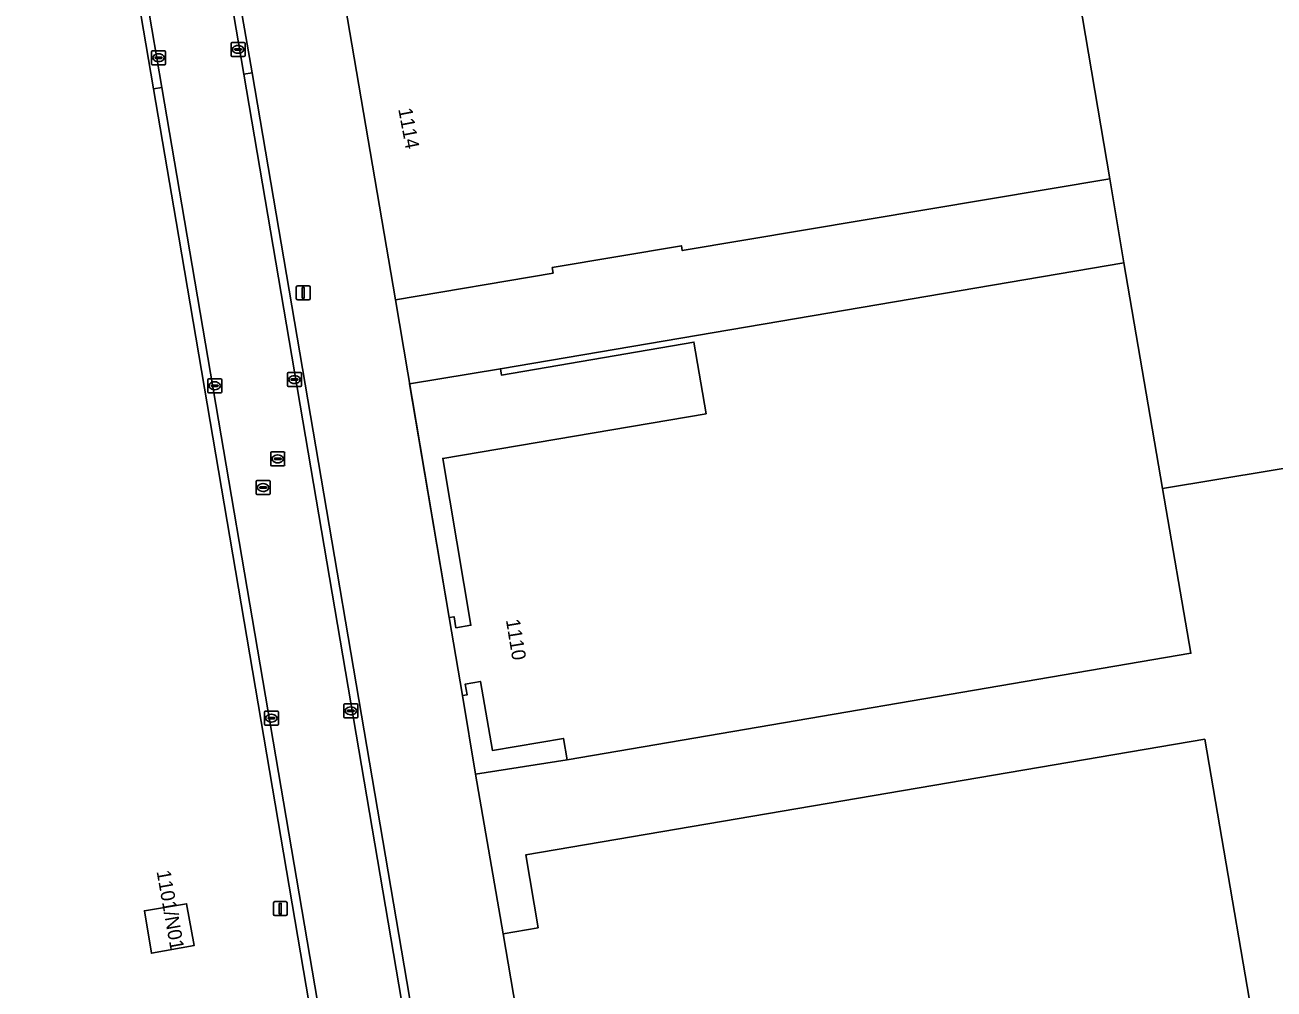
# Model space of a CAD drawing. Extents: x 154324 to 155744, y 382937 to 384188.
# Drawn here: x 154922.2 to 155011.6, y 383294.5 to 383363.4 of the extents above; entities that cross this region are included whole.
import ezdxf

# ---------------------------------------------------------------- set-up
doc = ezdxf.new("R2010")
doc.units = 0
for name, color, linetype in [('IMGEO_Erf', 7, 'Continuous'), ('IMGEO_Grasland_agrarisch', 7, 'Continuous'), ('IMGEO_Kolk', 7, 'Continuous'), ('IMGEO_Lichtmast', 7, 'Continuous'), ('IMGEO_Pand', 7, 'Continuous'), ('IMGEO_Pand_nummerreeks', 7, 'Continuous'), ('IMGEO_Pand_overbouw', 7, 'Continuous'), ('IMGEO_Parkeervlak_open', 7, 'Continuous'), ('IMGEO_Rijbaan_lokaal_gesloten', 7, 'Continuous'), ('IMGEO_Rijbaan_lokaal_open', 7, 'Continuous'), ('IMGEO_Rioolput', 7, 'Continuous')]:
    doc.layers.add(name, color=color, linetype=linetype)

msp = doc.modelspace()

# ---------------------------------------------------------------- linework, layer by layer
at = {"layer": 'IMGEO_Erf'}
for points in [[(154957.636, 383205.007), (154955.126, 383219.621), (154933.063, 383349.385), (154931.446, 383358.867), (154880.326, 383658.587)], [(155062.526, 383340.029), (155003.646, 383330.283), (155005.673, 383318.494), (154961.037, 383310.872), (154960.776, 383312.399), (154955.689, 383311.55), (154954.834, 383316.483), (154953.74, 383316.294), (154953.892, 383315.524), (154953.555, 383315.462), (154954.479, 383309.839), (154956.449, 383298.428), (154958.963, 383298.857), (154958.072, 383304.074), (155006.663, 383312.344), (155011.213, 383285.747), (154970.24, 383278.793), (154971.18, 383273.272), (154961.04, 383271.548), (154962.295, 383264.145), (155007.491, 383271.866), (155014.059, 383233.409)]]:
    msp.add_lwpolyline(points, dxfattribs=at)
for points in [[(154970.103, 383340.756), (154956.338, 383338.399), (154956.261, 383338.852), (155000.868, 383346.436), (154999.878, 383352.447), (154969.278, 383347.303), (154969.219, 383347.653), (154959.969, 383346.088), (154960.036, 383345.69), (154948.75, 383343.779), (154952.604, 383321.047), (154952.949, 383321.105), (154953.081, 383320.316), (154954.156, 383320.496), (154952.132, 383332.433), (154970.973, 383335.629)], [(154930.785, 383300.07), (154933.808, 383300.574), (154934.341, 383297.582), (154931.29, 383297.039)]]:
    msp.add_lwpolyline(points, close=True, dxfattribs=at)
at = {"layer": 'IMGEO_Grasland_agrarisch'}
msp.add_lwpolyline([(154995.109, 383380.559), (154999.878, 383352.447), (155000.868, 383346.436), (155003.646, 383330.283), (155062.526, 383340.029), (155067.422, 383340.839), (155069.458, 383341.15), (155069.432, 383341.538), (155066.213, 383389.857)], dxfattribs=at)
at = {"layer": 'IMGEO_Kolk'}
for p, q in [((154931.301, 383360.675), (154931.301, 383361.527)), ((154931.376, 383361.601), (154932.228, 383361.601)), ((154931.789, 383361.381), (154931.814, 383361.381)), ((154932.302, 383361.527), (154932.302, 383360.675)), ((154936.986, 383361.271), (154936.986, 383362.123)), ((154937.061, 383362.197), (154937.913, 383362.197)), ((154937.245, 383361.691), (154937.245, 383361.703)), ((154937.683, 383361.654), (154937.285, 383361.654)), ((154937.288, 383361.74), (154937.686, 383361.74)), ((154937.497, 383361.417), (154937.472, 383361.417)), ((154937.474, 383361.977), (154937.499, 383361.977)), ((154937.729, 383361.703), (154937.729, 383361.691)), ((154937.987, 383362.123), (154937.987, 383361.271)), ((154932.228, 383360.601), (154931.376, 383360.601)), ((154931.56, 383361.095), (154931.56, 383361.107)), ((154931.998, 383361.058), (154931.6, 383361.058)), ((154931.603, 383361.144), (154932.001, 383361.144)), ((154931.812, 383360.821), (154931.787, 383360.821)), ((154932.044, 383361.107), (154932.044, 383361.095)), ((154937.913, 383361.197), (154937.061, 383361.197)), ((154935.395, 383338.133), (154936.247, 383338.133)), ((154941.026, 383337.649), (154941.026, 383338.501)), ((154941.101, 383338.575), (154941.953, 383338.575)), ((154941.514, 383338.355), (154941.539, 383338.355)), ((154942.027, 383338.501), (154942.027, 383337.649)), ((154935.32, 383337.207), (154935.32, 383338.059)), ((154935.579, 383337.627), (154935.579, 383337.639)), ((154936.017, 383337.59), (154935.619, 383337.59)), ((154935.622, 383337.676), (154936.02, 383337.676)), ((154935.831, 383337.353), (154935.806, 383337.353)), ((154935.808, 383337.913), (154935.833, 383337.913)), ((154936.063, 383337.639), (154936.063, 383337.627)), ((154936.321, 383338.059), (154936.321, 383337.207)), ((154941.953, 383337.575), (154941.101, 383337.575)), ((154941.285, 383338.069), (154941.285, 383338.081)), ((154941.723, 383338.032), (154941.325, 383338.032)), ((154941.328, 383338.118), (154941.726, 383338.118)), ((154941.537, 383337.795), (154941.512, 383337.795)), ((154941.769, 383338.081), (154941.769, 383338.069)), ((154936.247, 383337.133), (154935.395, 383337.133)), ((154939.374, 383313.426), (154939.374, 383314.278)), ((154939.449, 383314.352), (154940.301, 383314.352)), ((154939.862, 383314.132), (154939.887, 383314.132)), ((154940.375, 383314.278), (154940.375, 383313.426)), ((154945.059, 383313.946), (154945.059, 383314.798)), ((154945.134, 383314.872), (154945.986, 383314.872)), ((154945.318, 383314.366), (154945.318, 383314.378)), ((154945.756, 383314.329), (154945.358, 383314.329)), ((154945.361, 383314.415), (154945.759, 383314.415)), ((154945.57, 383314.092), (154945.545, 383314.092)), ((154945.547, 383314.652), (154945.572, 383314.652)), ((154945.802, 383314.378), (154945.802, 383314.366)), ((154946.06, 383314.798), (154946.06, 383313.946)), ((154940.301, 383313.352), (154939.449, 383313.352)), ((154939.633, 383313.846), (154939.633, 383313.858)), ((154940.071, 383313.809), (154939.673, 383313.809)), ((154939.676, 383313.895), (154940.074, 383313.895)), ((154939.885, 383313.572), (154939.86, 383313.572)), ((154940.117, 383313.858), (154940.117, 383313.846)), ((154945.986, 383313.872), (154945.134, 383313.872))]:
    msp.add_line(p, q, dxfattribs=at)
for points in [[(154931.301, 383360.675), (154931.301, 383361.527)], [(154931.376, 383361.601), (154932.228, 383361.601)], [(154932.302, 383361.527), (154932.302, 383360.675)], [(154936.986, 383361.271), (154936.986, 383362.123)], [(154937.061, 383362.197), (154937.913, 383362.197)], [(154937.987, 383362.123), (154937.987, 383361.271)], [(154932.228, 383360.601), (154931.376, 383360.601)], [(154937.913, 383361.197), (154937.061, 383361.197)], [(154935.395, 383338.133), (154936.247, 383338.133)], [(154941.026, 383337.649), (154941.026, 383338.501)], [(154941.101, 383338.575), (154941.953, 383338.575)], [(154942.027, 383338.501), (154942.027, 383337.649)], [(154935.32, 383337.207), (154935.32, 383338.059)], [(154936.321, 383338.059), (154936.321, 383337.207)], [(154941.953, 383337.575), (154941.101, 383337.575)], [(154936.247, 383337.133), (154935.395, 383337.133)], [(154939.374, 383313.426), (154939.374, 383314.278)], [(154939.449, 383314.352), (154940.301, 383314.352)], [(154940.375, 383314.278), (154940.375, 383313.426)], [(154945.059, 383313.946), (154945.059, 383314.798)], [(154945.134, 383314.872), (154945.986, 383314.872)], [(154946.06, 383314.798), (154946.06, 383313.946)], [(154940.301, 383313.352), (154939.449, 383313.352)], [(154945.986, 383313.872), (154945.134, 383313.872)]]:
    msp.add_lwpolyline(points, dxfattribs=at)
for centre, radius, start, end in [((154931.378, 383361.525), 0.0765, 91.55205, 178.44795), ((154931.378, 383361.525), 0.0765, 91.55205, 178.44795), ((154932.226, 383361.525), 0.0765, 1.55205, 88.44795), ((154932.226, 383361.525), 0.0765, 1.55205, 88.44795), ((154937.063, 383362.121), 0.0765, 91.55205, 178.44795), ((154937.063, 383362.121), 0.0765, 91.55205, 178.44795), ((154937.285, 383361.7), 0.0403, 85.87752, 175.75265), ((154937.282, 383361.69), 0.0366, 178.93798, 274.71019), ((154937.686, 383361.697), 0.043, 264.86636, 352.45326), ((154937.69, 383361.702), 0.0386, 1.73085, 96.63898), ((154937.911, 383362.121), 0.0765, 1.55205, 88.44795), ((154937.911, 383362.121), 0.0765, 1.55205, 88.44795), ((154931.378, 383360.677), 0.0765, 181.55205, 268.44795), ((154931.378, 383360.677), 0.0765, 181.55205, 268.44795), ((154931.6, 383361.104), 0.0403, 85.87752, 175.75265), ((154931.597, 383361.094), 0.0366, 178.93798, 274.71019), ((154932.001, 383361.101), 0.043, 264.86636, 352.45326), ((154932.005, 383361.106), 0.0386, 1.73085, 96.63898), ((154932.226, 383360.677), 0.0765, 271.55205, 358.44795), ((154932.226, 383360.677), 0.0765, 271.55205, 358.44795), ((154937.063, 383361.273), 0.0765, 181.55205, 268.44795), ((154937.063, 383361.273), 0.0765, 181.55205, 268.44795), ((154937.911, 383361.273), 0.0765, 271.55205, 358.44795), ((154937.911, 383361.273), 0.0765, 271.55205, 358.44795), ((154935.397, 383338.057), 0.0765, 91.55205, 178.44795), ((154935.397, 383338.057), 0.0765, 91.55205, 178.44795), ((154936.245, 383338.057), 0.0765, 1.55205, 88.44795), ((154936.245, 383338.057), 0.0765, 1.55205, 88.44795), ((154941.103, 383338.499), 0.0765, 91.55205, 178.44795), ((154941.103, 383338.499), 0.0765, 91.55205, 178.44795), ((154941.951, 383338.499), 0.0765, 1.55205, 88.44795), ((154941.951, 383338.499), 0.0765, 1.55205, 88.44795), ((154935.619, 383337.636), 0.0403, 85.87752, 175.75265), ((154935.616, 383337.626), 0.0366, 178.93798, 274.71019), ((154936.02, 383337.633), 0.043, 264.86636, 352.45326), ((154936.024, 383337.638), 0.0386, 1.73085, 96.63898), ((154941.103, 383337.651), 0.0765, 181.55205, 268.44795), ((154941.103, 383337.651), 0.0765, 181.55205, 268.44795), ((154941.325, 383338.078), 0.0403, 85.87752, 175.75265), ((154941.322, 383338.068), 0.0366, 178.93798, 274.71019), ((154941.726, 383338.075), 0.043, 264.86636, 352.45326), ((154941.73, 383338.08), 0.0386, 1.73085, 96.63898), ((154941.951, 383337.651), 0.0765, 271.55205, 358.44795), ((154941.951, 383337.651), 0.0765, 271.55205, 358.44795), ((154935.397, 383337.209), 0.0765, 181.55205, 268.44795), ((154935.397, 383337.209), 0.0765, 181.55205, 268.44795), ((154936.245, 383337.209), 0.0765, 271.55205, 358.44795), ((154936.245, 383337.209), 0.0765, 271.55205, 358.44795), ((154939.451, 383314.276), 0.0765, 91.55205, 178.44795), ((154939.451, 383314.276), 0.0765, 91.55205, 178.44795), ((154940.299, 383314.276), 0.0765, 1.55205, 88.44795), ((154940.299, 383314.276), 0.0765, 1.55205, 88.44795), ((154945.136, 383314.796), 0.0765, 91.55205, 178.44795), ((154945.136, 383314.796), 0.0765, 91.55205, 178.44795), ((154945.358, 383314.375), 0.0403, 85.87752, 175.75265), ((154945.355, 383314.365), 0.0366, 178.93798, 274.71019), ((154945.759, 383314.372), 0.043, 264.86636, 352.45326), ((154945.763, 383314.377), 0.0386, 1.73085, 96.63898), ((154945.984, 383314.796), 0.0765, 1.55205, 88.44795), ((154945.984, 383314.796), 0.0765, 1.55205, 88.44795), ((154939.451, 383313.428), 0.0765, 181.55205, 268.44795), ((154939.451, 383313.428), 0.0765, 181.55205, 268.44795), ((154939.673, 383313.855), 0.0403, 85.87752, 175.75265), ((154939.67, 383313.845), 0.0366, 178.93798, 274.71019), ((154940.074, 383313.852), 0.043, 264.86636, 352.45326), ((154940.078, 383313.857), 0.0386, 1.73085, 96.63898), ((154940.299, 383313.428), 0.0765, 271.55205, 358.44795), ((154940.299, 383313.428), 0.0765, 271.55205, 358.44795), ((154945.136, 383313.948), 0.0765, 181.55205, 268.44795), ((154945.136, 383313.948), 0.0765, 181.55205, 268.44795), ((154945.984, 383313.948), 0.0765, 271.55205, 358.44795), ((154945.984, 383313.948), 0.0765, 271.55205, 358.44795)]:
    msp.add_arc(centre, radius, start, end, dxfattribs=at)
for centre, major_axis, ratio, start_param, end_param in [((154931.788, 383361.101), (-0.387, 0.002), 0.722429, 4.712389, 7.853982), ((154931.813, 383361.101), (-0.39, 0.002), 0.717154, 1.570796, 4.712389), ((154937.473, 383361.697), (-0.387, 0.002), 0.722429, 4.712389, 7.853982), ((154937.498, 383361.697), (-0.39, 0.002), 0.717154, 1.570796, 4.712389), ((154941.513, 383338.075), (-0.387, 0.002), 0.722429, 4.712389, 7.853982), ((154941.538, 383338.075), (-0.39, 0.002), 0.717154, 1.570796, 4.712389), ((154935.807, 383337.633), (-0.387, 0.002), 0.722429, 4.712389, 7.853982), ((154935.832, 383337.633), (-0.39, 0.002), 0.717154, 1.570796, 4.712389), ((154939.861, 383313.852), (-0.387, 0.002), 0.722429, 4.712389, 7.853982), ((154939.886, 383313.852), (-0.39, 0.002), 0.717154, 1.570796, 4.712389), ((154945.546, 383314.372), (-0.387, 0.002), 0.722429, 4.712389, 7.853982), ((154945.571, 383314.372), (-0.39, 0.002), 0.717154, 1.570796, 4.712389)]:
    msp.add_ellipse(centre, major_axis=major_axis, ratio=ratio, start_param=start_param, end_param=end_param, dxfattribs=at)
at = {"layer": 'IMGEO_Lichtmast'}
for p, q in [((154941.658, 383343.88), (154941.658, 383344.68)), ((154941.658, 383344.68), (154941.658, 383343.88)), ((154941.758, 383344.78), (154942.548, 383344.78)), ((154942.548, 383344.78), (154941.758, 383344.78)), ((154942.648, 383344.68), (154942.648, 383343.88)), ((154942.648, 383343.88), (154942.648, 383344.68)), ((154942.548, 383343.78), (154941.758, 383343.78)), ((154941.758, 383343.78), (154942.548, 383343.78)), ((154940.014, 383299.826), (154940.014, 383300.626)), ((154940.014, 383300.626), (154940.014, 383299.826)), ((154940.114, 383300.726), (154940.904, 383300.726)), ((154940.904, 383300.726), (154940.114, 383300.726)), ((154941.004, 383300.626), (154941.004, 383299.826)), ((154941.004, 383299.826), (154941.004, 383300.626)), ((154940.904, 383299.726), (154940.114, 383299.726)), ((154940.114, 383299.726), (154940.904, 383299.726))]:
    msp.add_line(p, q, dxfattribs=at)
for points in [[(154942.078, 383344.655), (154942.228, 383344.655), (154942.228, 383343.905), (154942.078, 383343.905), (154942.078, 383344.655)], [(154940.434, 383300.601), (154940.584, 383300.601), (154940.584, 383299.851), (154940.434, 383299.851), (154940.434, 383300.601)]]:
    msp.add_lwpolyline(points, dxfattribs=at)
for centre, start, end in [((154941.758, 383344.68), 90, 180), ((154941.758, 383344.68), 90, 180), ((154942.548, 383344.68), 0, 90), ((154942.548, 383344.68), 360, 90), ((154941.758, 383343.88), 180, 270), ((154941.758, 383343.88), 180, 270), ((154942.548, 383343.88), 270, 0), ((154942.548, 383343.88), 270, 0), ((154940.114, 383300.626), 90, 180), ((154940.114, 383300.626), 90, 180), ((154940.904, 383300.626), 0, 90), ((154940.904, 383300.626), 360, 90), ((154940.114, 383299.826), 180, 270), ((154940.114, 383299.826), 180, 270), ((154940.904, 383299.826), 270, 0), ((154940.904, 383299.826), 270, 0)]:
    msp.add_arc(centre, 0.1, start, end, dxfattribs=at)
at = {"layer": 'IMGEO_Pand'}
for points in [[(154995.109, 383380.559), (154964.539, 383375.316), (154965.468, 383369.782), (154944.925, 383366.268), (154944.993, 383365.869), (154948.75, 383343.779), (154960.036, 383345.69), (154959.969, 383346.088), (154969.219, 383347.653), (154969.278, 383347.303), (154999.878, 383352.447)], [(155000.868, 383346.436), (154956.261, 383338.852), (154956.338, 383338.399), (154970.103, 383340.756), (154970.973, 383335.629), (154952.132, 383332.433), (154954.156, 383320.496), (154953.081, 383320.316), (154952.949, 383321.105), (154952.604, 383321.047), (154953.555, 383315.462), (154953.892, 383315.524), (154953.74, 383316.294), (154954.834, 383316.483), (154955.689, 383311.55), (154960.776, 383312.399), (154961.037, 383310.872), (155005.673, 383318.494), (155003.646, 383330.283)], [(154958.072, 383304.074), (154958.963, 383298.857), (154956.449, 383298.428), (154961.04, 383271.548), (154971.18, 383273.272), (154970.24, 383278.793), (155011.213, 383285.747), (155006.663, 383312.344)], [(154931.29, 383297.039), (154934.341, 383297.582), (154933.808, 383300.574), (154930.785, 383300.07)]]:
    msp.add_lwpolyline(points, close=True, dxfattribs=at)
at = {"layer": 'IMGEO_Pand_overbouw'}
for points in [[(154956.261, 383338.852), (154949.764, 383337.775), (154952.604, 383321.047), (154952.949, 383321.105), (154953.081, 383320.316), (154954.156, 383320.496), (154952.132, 383332.433), (154970.973, 383335.629), (154970.103, 383340.756), (154956.338, 383338.399)], [(154961.037, 383310.872), (154960.776, 383312.399), (154955.689, 383311.55), (154954.834, 383316.483), (154953.74, 383316.294), (154953.892, 383315.524), (154953.555, 383315.462), (154954.479, 383309.839)]]:
    msp.add_lwpolyline(points, close=True, dxfattribs=at)
at = {"layer": 'IMGEO_Parkeervlak_open'}
msp.add_lwpolyline([(154970.556, 383221.2), (154970.312, 383222.697), (154969.397, 383222.533), (154962.295, 383264.145), (154961.04, 383271.548), (154956.449, 383298.428), (154954.479, 383309.839), (154953.555, 383315.462), (154952.604, 383321.047), (154948.75, 383343.779), (154944.993, 383365.869), (154944.925, 383366.268), (154965.468, 383369.782), (154964.539, 383375.316), (154941.3, 383371.33), (154939.601, 383371.039), (154936.699, 383370.542), (154936.71, 383370.477), (154937.698, 383364.674), (154938.491, 383360.02), (154942.478, 383336.616), (154962.428, 383219.494)], dxfattribs=at)
at = {"layer": 'IMGEO_Rijbaan_lokaal_gesloten'}
for points in [[(154854.425, 383814.31), (154854.653, 383812.991), (154854.813, 383812.024), (154858.483, 383790.497), (154869.559, 383725.258), (154869.596, 383725.133), (154932.04, 383358.964), (154933.662, 383349.45), (154956.051, 383217.962), (154957.681, 383208.024), (154958.22, 383204.737)], [(154961.836, 383219.4), (154937.891, 383359.922), (154875.734, 383724.688)]]:
    msp.add_lwpolyline(points, dxfattribs=at)
at = {"layer": 'IMGEO_Rijbaan_lokaal_open'}
for points in [[(154859.21, 383821.776), (154860.592, 383813.666), (154872.994, 383740.868), (154875.261, 383727.607), (154875.734, 383724.688), (154937.891, 383359.922), (154938.491, 383360.02), (154937.698, 383364.674), (154936.71, 383370.477), (154936.699, 383370.542), (154936.688, 383370.604), (154886.005, 383668.098)], [(154853.936, 383813.593), (154856.176, 383800.396), (154857.871, 383790.412), (154868.954, 383725.158), (154878.393, 383669.904), (154880.297, 383658.755), (154880.326, 383658.587), (154931.446, 383358.867), (154932.04, 383358.964), (154869.596, 383725.133), (154869.559, 383725.258), (154858.483, 383790.497), (154854.813, 383812.024), (154854.653, 383812.991), (154854.425, 383814.31)], [(154938.491, 383360.02), (154937.891, 383359.922), (154961.836, 383219.4)], [(154962.428, 383219.494), (154942.478, 383336.616), (154938.491, 383360.02)], [(154958.22, 383204.737), (154957.681, 383208.024), (154956.051, 383217.962), (154933.662, 383349.45), (154932.04, 383358.964), (154931.446, 383358.867), (154933.063, 383349.385), (154955.126, 383219.621), (154957.636, 383205.007)]]:
    msp.add_lwpolyline(points, dxfattribs=at)
at = {"layer": 'IMGEO_Rioolput'}
for p, q in [((154939.823, 383331.974), (154939.823, 383332.826)), ((154939.898, 383332.9), (154940.75, 383332.9)), ((154940.824, 383332.826), (154940.824, 383331.974)), ((154940.75, 383331.9), (154939.898, 383331.9)), ((154940.082, 383332.394), (154940.082, 383332.406)), ((154940.52, 383332.357), (154940.122, 383332.357)), ((154940.125, 383332.443), (154940.523, 383332.443)), ((154940.334, 383332.12), (154940.309, 383332.12)), ((154940.311, 383332.68), (154940.336, 383332.68)), ((154940.566, 383332.406), (154940.566, 383332.394)), ((154938.778, 383329.924), (154938.778, 383330.776)), ((154938.853, 383330.85), (154939.705, 383330.85)), ((154939.037, 383330.344), (154939.037, 383330.356)), ((154939.475, 383330.307), (154939.077, 383330.307)), ((154939.08, 383330.393), (154939.478, 383330.393)), ((154939.266, 383330.63), (154939.291, 383330.63)), ((154939.521, 383330.356), (154939.521, 383330.344)), ((154939.779, 383330.776), (154939.779, 383329.924)), ((154939.705, 383329.85), (154938.853, 383329.85)), ((154939.289, 383330.07), (154939.264, 383330.07))]:
    msp.add_line(p, q, dxfattribs=at)
for points in [[(154939.823, 383331.974), (154939.823, 383332.826)], [(154939.898, 383332.9), (154940.75, 383332.9)], [(154940.824, 383332.826), (154940.824, 383331.974)], [(154940.75, 383331.9), (154939.898, 383331.9)], [(154938.778, 383329.924), (154938.778, 383330.776)], [(154938.853, 383330.85), (154939.705, 383330.85)], [(154939.779, 383330.776), (154939.779, 383329.924)], [(154939.705, 383329.85), (154938.853, 383329.85)]]:
    msp.add_lwpolyline(points, dxfattribs=at)
for centre, radius, start, end in [((154939.9, 383332.824), 0.0765, 91.55205, 178.44795), ((154939.9, 383332.824), 0.0765, 91.55205, 178.44795), ((154940.748, 383332.824), 0.0765, 1.55205, 88.44795), ((154940.748, 383332.824), 0.0765, 1.55205, 88.44795), ((154939.9, 383331.976), 0.0765, 181.55205, 268.44795), ((154939.9, 383331.976), 0.0765, 181.55205, 268.44795), ((154940.122, 383332.403), 0.0403, 85.87752, 175.75265), ((154940.119, 383332.393), 0.0366, 178.93798, 274.71019), ((154940.523, 383332.4), 0.043, 264.86636, 352.45326), ((154940.527, 383332.405), 0.0386, 1.73085, 96.63898), ((154940.748, 383331.976), 0.0765, 271.55205, 358.44795), ((154940.748, 383331.976), 0.0765, 271.55205, 358.44795), ((154938.855, 383330.774), 0.0765, 91.55205, 178.44795), ((154938.855, 383330.774), 0.0765, 91.55205, 178.44795), ((154939.077, 383330.353), 0.0403, 85.87752, 175.75265), ((154939.074, 383330.343), 0.0366, 178.93798, 274.71019), ((154939.478, 383330.35), 0.043, 264.86636, 352.45326), ((154939.482, 383330.355), 0.0386, 1.73085, 96.63898), ((154939.703, 383330.774), 0.0765, 1.55205, 88.44795), ((154939.703, 383330.774), 0.0765, 1.55205, 88.44795), ((154938.855, 383329.926), 0.0765, 181.55205, 268.44795), ((154938.855, 383329.926), 0.0765, 181.55205, 268.44795), ((154939.703, 383329.926), 0.0765, 271.55205, 358.44795), ((154939.703, 383329.926), 0.0765, 271.55205, 358.44795)]:
    msp.add_arc(centre, radius, start, end, dxfattribs=at)
for centre, major_axis, ratio, start_param, end_param in [((154940.31, 383332.4), (-0.387, 0.002), 0.722429, 4.712389, 7.853982), ((154940.335, 383332.4), (-0.39, 0.002), 0.717154, 1.570796, 4.712389), ((154939.265, 383330.35), (-0.387, 0.002), 0.722429, 4.712389, 7.853982), ((154939.29, 383330.35), (-0.39, 0.002), 0.717154, 1.570796, 4.712389)]:
    msp.add_ellipse(centre, major_axis=major_axis, ratio=ratio, start_param=start_param, end_param=end_param, dxfattribs=at)

# ---------------------------------------------------------------- texts
at = {"layer": 'IMGEO_Pand_nummerreeks'}
for s, rotation, p in [('1114', 280.81673, (154948.945, 383357.424)), ('1110', 279.28457, (154956.652, 383320.871)), ('1101/N01', 280.10844, (154931.653, 383302.889))]:
    msp.add_text(s, height=1, rotation=rotation, dxfattribs=at).set_placement(p)

doc.saveas('drawing.dxf')
